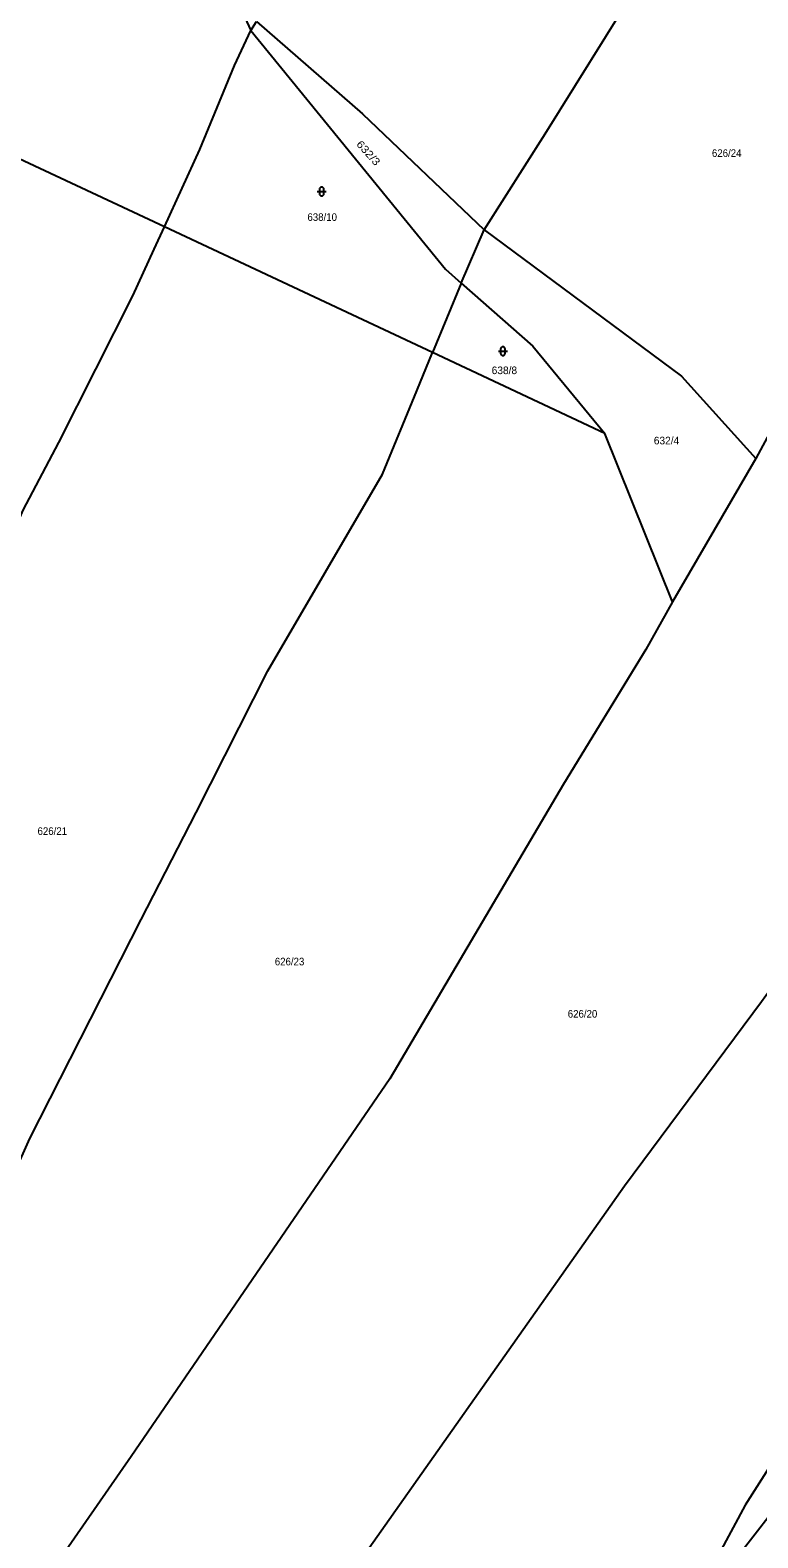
# Model space of a CAD drawing. Extents: x -687135 to -684370, y -1007309 to -1005782.
# Drawn here: x -685073.8 to -684911.1, y -1006317.9 to -1005980.6 of the extents above; entities that cross this region are included whole.
import ezdxf

# ---------------------------------------------------------------- set-up
doc = ezdxf.new("R2010")
doc.units = 0
doc.header["$LTSCALE"] = 0.68
doc.layers.add('1', color=7, linetype='Continuous', lineweight=25)
doc.layers.add('3', color=7, linetype='Continuous', lineweight=25)
doc.layers.add('2', color=7, linetype='Continuous')

msp = doc.modelspace()

# ---------------------------------------------------------------- linework, layer by layer
at = {"layer": '1'}
for p, q in [((-684983.8, -1006052.73), (-685043.78, -1006024.6)), ((-684977.39, -1006037.18), (-684972.24, -1006025.24)), ((-684977.39, -1006037.18), (-684983.8, -1006052.73))]:
    msp.add_line(p, q, dxfattribs=at)
for points in [[(-685090.53, -1005950.59), (-685032.5, -1005955.2), (-685033.24, -1005961.49), (-685024.44, -1005980.64), (-685023.21, -1005978.63)], [(-684972.24, -1006025.24), (-684958.61, -1006003.79), (-684924.69, -1005949.22)], [(-685043.78, -1006024.6), (-685035.85, -1006007.25), (-685028.13, -1005988.48), (-685024.44, -1005980.64)], [(-685024.44, -1005980.64), (-684980.9, -1006034.09), (-684977.39, -1006037.18)], [(-685023.21, -1005978.63), (-684999.45, -1005999.31), (-684972.24, -1006025.24)], [(-685043.78, -1006024.6), (-685094.94, -1006000.61), (-685110.34, -1005996.38), (-685115.38, -1005999.81)], [(-684867.33, -1005996.85), (-684871.56, -1006003.53), (-684886.02, -1006029.12), (-684911.48, -1006076.41), (-684930.17, -1006108.46)], [(-685145.13, -1006274.7), (-685136.85, -1006250.38), (-685091.37, -1006125.23), (-685075.37, -1006088.01), (-685067.37, -1006072.83), (-685050.82, -1006039.99), (-685046.05, -1006029.56), (-685043.78, -1006024.6)], [(-684972.24, -1006025.24), (-684928.15, -1006058.01), (-684911.48, -1006076.41)], [(-684977.39, -1006037.18), (-684961.39, -1006051.28), (-684945.27, -1006070.8)], [(-685117.08, -1006310.67), (-685097.85, -1006278.37), (-685080.32, -1006242.98), (-685073.88, -1006228.61), (-685048.94, -1006179.58), (-685036.71, -1006155.62), (-685020.67, -1006123.9), (-684995.04, -1006079.93), (-684987.31, -1006061.26), (-684983.8, -1006052.73)], [(-684930.17, -1006108.46), (-684945.27, -1006070.8), (-684983.8, -1006052.73)], [(-684930.17, -1006108.46), (-684936.09, -1006119.13), (-684954.55, -1006149.28), (-684993.37, -1006215.25), (-685051.21, -1006299.76), (-685074, -1006332.62), (-685091.4, -1006354.8)], [(-685067.76, -1006407.52), (-685012.1, -1006340.15), (-684940.88, -1006239.13), (-684910.26, -1006197.91), (-684889.9, -1006169.75), (-684877.93, -1006152.74), (-684876.78, -1006150.79)], [(-684856.23, -1006219.78), (-684868.36, -1006236.18), (-684877.16, -1006249.29), (-684887.91, -1006266.51), (-684898.63, -1006286.6), (-684913.88, -1006310.63), (-684919.75, -1006321.58), (-684931.87, -1006339.19), (-684939.11, -1006350.34), (-684952.01, -1006369.9), (-684965.12, -1006392.2), (-684970.59, -1006402.96), (-684973.76, -1006410.29), (-684980.32, -1006434.42)], [(-684900.57, -1006302.99), (-684907.23, -1006311.42), (-684918.18, -1006325.47), (-684932.07, -1006347.35), (-684944, -1006366.68), (-684955.53, -1006384.87), (-684969.03, -1006410.25), (-684975.28, -1006437.24), (-684977.83, -1006474.8), (-684979.92, -1006493.97)]]:
    msp.add_lwpolyline(points, dxfattribs=at)
at = {"layer": '3'}
for p, q in [((-685009.601, -1006016.671), (-685007.599, -1006016.671)), ((-685009.101, -1006016.171), (-685009.101, -1006017.172)), ((-685008.099, -1006017.172), (-685008.099, -1006016.171)), ((-684968.581, -1006051.901), (-684968.581, -1006052.902)), ((-684967.579, -1006052.902), (-684967.579, -1006051.901)), ((-684969.081, -1006052.401), (-684967.079, -1006052.401))]:
    msp.add_line(p, q, dxfattribs=at)
for centre, start, end in [((-685008.6, -1006016.1709), 0, 180), ((-685008.6, -1006017.1709), 180, 359.98789), ((-684968.08, -1006051.9009), 0, 180), ((-684968.08, -1006052.9009), 180, 359.98789)]:
    msp.add_arc(centre, 0.5, start, end, dxfattribs=at)

# ---------------------------------------------------------------- texts
at = {"layer": '2', "width": 1.15}
msp.add_text('632/3', height=1.7, rotation=312, dxfattribs=at).set_placement((-685000.981, -1006006.198))
at = {"layer": '2', "width": 0.95}
for s, p in [('626/24', (-684921.33, -1006008.94)), ('638/10', (-685011.79, -1006023.25)), ('626/21', (-685072.15, -1006160.64)), ('626/23', (-685019.09, -1006189.83)), ('626/20', (-684953.57, -1006201.53))]:
    msp.add_text(s, height=1.7, dxfattribs=at).set_placement(p)
at = {"layer": '2'}
for s, p in [('638/8', (-684970.59, -1006057.539)), ('632/4', (-684934.33, -1006073.25))]:
    msp.add_text(s, height=1.7, dxfattribs=at).set_placement(p)

doc.saveas('drawing.dxf')
